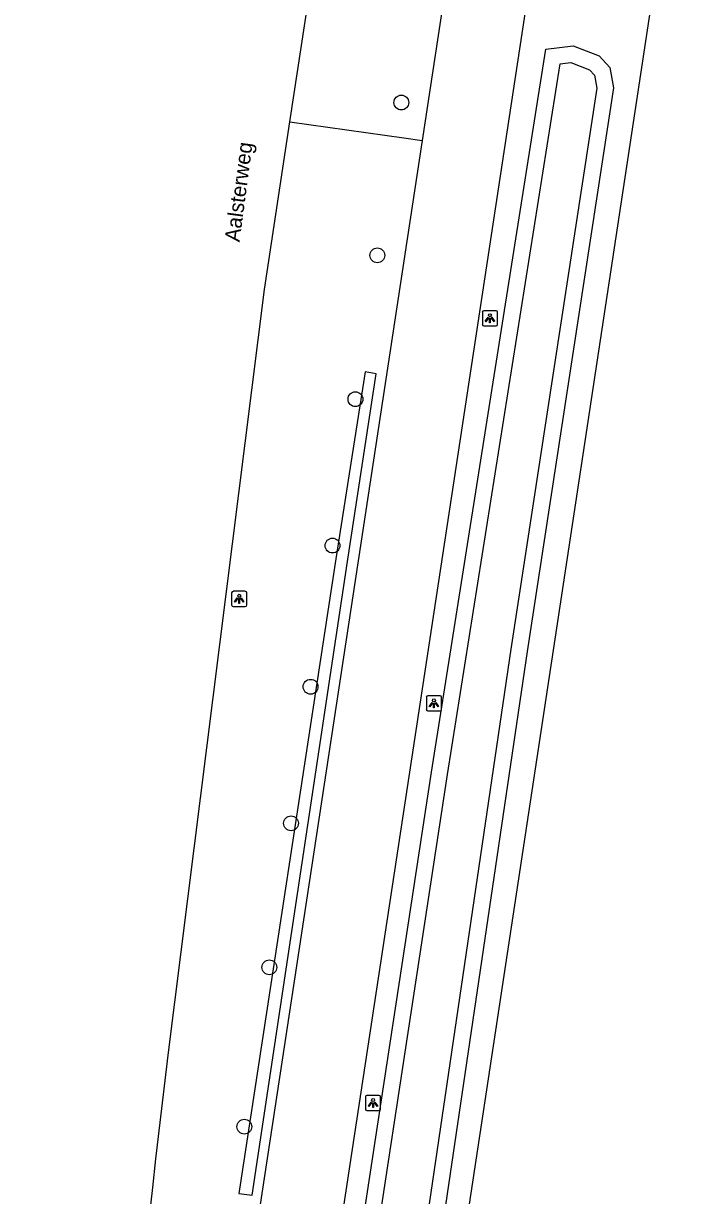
# Model space of a CAD drawing. Extents: x 161486 to 162249, y 379484 to 380829.
# Drawn here: x 161540.1 to 161583.9, y 379840.5 to 379917.8 of the extents above; entities that cross this region are included whole.
import ezdxf

# ---------------------------------------------------------------- set-up
doc = ezdxf.new("R2010")
doc.units = 0
for name, color, linetype in [('IMGEO_Berm_groen', 7, 'Continuous'), ('IMGEO_Boom', 7, 'Continuous'), ('IMGEO_Gemengd_bos', 7, 'Continuous'), ('IMGEO_Groenvoorziening', 7, 'Continuous'), ('IMGEO_Haag', 7, 'Continuous'), ('IMGEO_Lichtpunt', 7, 'Continuous'), ('IMGEO_Openbare_ruimte_label', 7, 'Continuous'), ('IMGEO_Rijbaan_lokaal_open', 7, 'Continuous'), ('IMGEO_Rijbaan_regionaal_gesloten', 7, 'Continuous'), ('IMGEO_Waterloop', 7, 'Continuous')]:
    doc.layers.add(name, color=color, linetype=linetype)

msp = doc.modelspace()

# ---------------------------------------------------------------- linework, layer by layer
at = {"layer": 'IMGEO_Berm_groen'}
msp.add_lwpolyline([(161557.693, 379911.327), (161565.21, 379910.272), (161566.417, 379910.103)], dxfattribs=at)
at = {"layer": 'IMGEO_Boom'}
for centre in [(161565.046, 379912.61), (161563.466, 379902.523), (161562.018, 379893.035), (161560.505, 379883.376), (161559.056, 379874.058), (161557.771, 379865.048), (161556.339, 379855.542), (161554.684, 379845.029)]:
    msp.add_circle(centre, 0.489, dxfattribs=at)
at = {"layer": 'IMGEO_Gemengd_bos'}
msp.add_lwpolyline([(161583.938, 379934.952), (161568.827, 379835.279), (161557.114, 379758.02)], dxfattribs=at)
at = {"layer": 'IMGEO_Groenvoorziening'}
msp.add_lwpolyline([(161579.042, 379913.572), (161573.346, 379876.388), (161565.066, 379820.159), (161564.384, 379818.933), (161559.643, 379819.959), (161567.034, 379868.426), (161574.594, 379916.137), (161576.379, 379916.357), (161578.094, 379915.687), (161578.809, 379914.928), (161579.042, 379913.572)], dxfattribs=at)
at = {"layer": 'IMGEO_Haag'}
msp.add_lwpolyline([(161561.497, 379882.333), (161563.397, 379894.707), (161562.657, 379894.836), (161560.722, 379882.51), (161554.328, 379840.615), (161555.212, 379840.511), (161561.497, 379882.333)], dxfattribs=at)
at = {"layer": 'IMGEO_Lichtpunt'}
for p, q in [((161571.296, 379898.87), (161570.488, 379898.87)), ((161571.296, 379898.87), (161570.488, 379898.87)), ((161570.394, 379898.775), (161570.394, 379897.968)), ((161570.394, 379898.775), (161570.394, 379897.968)), ((161571.39, 379897.968), (161571.39, 379898.775)), ((161571.39, 379897.968), (161571.39, 379898.775)), ((161570.488, 379897.874), (161571.296, 379897.874)), ((161570.488, 379897.874), (161571.296, 379897.874)), ((161554.752, 379880.356), (161553.944, 379880.356)), ((161554.752, 379880.356), (161553.944, 379880.356)), ((161553.85, 379880.261), (161553.85, 379879.454)), ((161553.85, 379880.261), (161553.85, 379879.454)), ((161554.846, 379879.454), (161554.846, 379880.261)), ((161554.846, 379879.454), (161554.846, 379880.261)), ((161553.944, 379879.36), (161554.752, 379879.36)), ((161553.944, 379879.36), (161554.752, 379879.36)), ((161566.698, 379873.365), (161566.698, 379872.558)), ((161566.698, 379873.365), (161566.698, 379872.558)), ((161567.6, 379873.46), (161566.792, 379873.46)), ((161567.6, 379873.46), (161566.792, 379873.46)), ((161567.694, 379872.558), (161567.694, 379873.365)), ((161567.694, 379872.558), (161567.694, 379873.365)), ((161566.792, 379872.464), (161567.6, 379872.464)), ((161566.792, 379872.464), (161567.6, 379872.464)), ((161563.587, 379847.089), (161562.779, 379847.089)), ((161563.587, 379847.089), (161562.779, 379847.089)), ((161562.685, 379846.994), (161562.685, 379846.187)), ((161562.685, 379846.994), (161562.685, 379846.187)), ((161563.681, 379846.187), (161563.681, 379846.994)), ((161563.681, 379846.187), (161563.681, 379846.994)), ((161562.779, 379846.093), (161563.587, 379846.093)), ((161562.779, 379846.093), (161563.587, 379846.093))]:
    msp.add_line(p, q, dxfattribs=at)
for points in [[(161570.768, 379898.439), (161570.807, 379898.411), (161570.619, 379898.149), (161570.581, 379898.176), (161570.768, 379898.439)], [(161570.87, 379898.391), (161570.917, 379898.391), (161570.917, 379898.069), (161570.87, 379898.069), (161570.87, 379898.391)], [(161570.98, 379898.411), (161571.018, 379898.438), (161571.205, 379898.176), (161571.166, 379898.148), (161570.98, 379898.411)], [(161554.224, 379879.925), (161554.263, 379879.897), (161554.075, 379879.635), (161554.037, 379879.662), (161554.224, 379879.925)], [(161554.326, 379879.877), (161554.373, 379879.877), (161554.373, 379879.555), (161554.326, 379879.555), (161554.326, 379879.877)], [(161554.436, 379879.897), (161554.474, 379879.924), (161554.661, 379879.662), (161554.622, 379879.634), (161554.436, 379879.897)], [(161567.072, 379873.029), (161567.111, 379873.001), (161566.923, 379872.739), (161566.885, 379872.766), (161567.072, 379873.029)], [(161567.174, 379872.981), (161567.221, 379872.981), (161567.221, 379872.659), (161567.174, 379872.659), (161567.174, 379872.981)], [(161567.284, 379873.001), (161567.322, 379873.028), (161567.509, 379872.766), (161567.47, 379872.738), (161567.284, 379873.001)], [(161563.059, 379846.658), (161563.098, 379846.63), (161562.91, 379846.368), (161562.872, 379846.395), (161563.059, 379846.658)], [(161563.161, 379846.61), (161563.208, 379846.61), (161563.208, 379846.288), (161563.161, 379846.288), (161563.161, 379846.61)], [(161563.271, 379846.63), (161563.309, 379846.657), (161563.496, 379846.395), (161563.457, 379846.367), (161563.271, 379846.63)]]:
    msp.add_lwpolyline(points, dxfattribs=at)
for centre in [(161570.893, 379898.573), (161554.349, 379880.059), (161567.197, 379873.163), (161563.184, 379846.792)]:
    msp.add_circle(centre, 0.0994, dxfattribs=at)
for centre, start, end in [((161570.488, 379898.775), 90, 180), ((161570.488, 379898.775), 90, 180), ((161571.296, 379898.775), 0, 90), ((161571.296, 379898.775), 0, 90), ((161570.488, 379897.968), 180, 270), ((161570.488, 379897.968), 180, 270), ((161571.296, 379897.968), 270, 0), ((161571.296, 379897.968), 270, 360), ((161553.944, 379880.261), 90, 180), ((161553.944, 379880.261), 90, 180), ((161554.752, 379880.261), 0, 90), ((161554.752, 379880.261), 0, 90), ((161553.944, 379879.454), 180, 270), ((161553.944, 379879.454), 180, 270), ((161554.752, 379879.454), 270, 0), ((161554.752, 379879.454), 270, 360), ((161566.792, 379873.365), 90, 180), ((161566.792, 379873.365), 90, 180), ((161567.6, 379873.365), 0, 90), ((161567.6, 379873.365), 0, 90), ((161566.792, 379872.558), 180, 270), ((161566.792, 379872.558), 180, 270), ((161567.6, 379872.558), 270, 0), ((161567.6, 379872.558), 270, 360), ((161562.779, 379846.994), 90, 180), ((161562.779, 379846.994), 90, 180), ((161563.587, 379846.994), 0, 90), ((161563.587, 379846.994), 0, 90), ((161562.779, 379846.187), 180, 270), ((161562.779, 379846.187), 180, 270), ((161563.587, 379846.187), 270, 0), ((161563.587, 379846.187), 270, 360)]:
    msp.add_arc(centre, 0.0946, start, end, dxfattribs=at)
at = {"layer": 'IMGEO_Rijbaan_lokaal_open'}
for points in [[(161574.263, 379936.392), (161574.118, 379934.45), (161574.401, 379931.306), (161574.489, 379927.649), (161574.039, 379923.973), (161560.773, 379836.759), (161558.436, 379821.396), (161558.059, 379819.043), (161557.417, 379814.852), (161556.702, 379809.458), (161556.07, 379805.38), (161554.769, 379796.716), (161550.698, 379765.372), (161550.328, 379761.55)], [(161568.671, 379924.979), (161568.639, 379924.714), (161566.417, 379910.103)], [(161566.417, 379910.103), (161555.385, 379837.579), (161553.583, 379825.732)]]:
    msp.add_lwpolyline(points, dxfattribs=at)
at = {"layer": 'IMGEO_Rijbaan_regionaal_gesloten'}
for points in [[(161557.693, 379911.327), (161561.114, 379933.819)], [(161540.108, 379760.615), (161541.483, 379775.689), (161542.991, 379790.84), (161543.902, 379799.222), (161544.154, 379801.546), (161544.174, 379801.742), (161544.225, 379802.254), (161545.482, 379814.716), (161546.135, 379819.933), (161546.428, 379824.038), (161546.834, 379827.017), (161547.079, 379827.822), (161548.103, 379836.152), (161548.651, 379841.02), (161548.842, 379842.908), (161549.676, 379849.933), (161556.011, 379900.267), (161557.693, 379911.327)], [(161546.834, 379827.017), (161547.079, 379827.822), (161548.103, 379836.152), (161548.651, 379841.02), (161548.842, 379842.908), (161549.676, 379849.933), (161556.011, 379900.267), (161557.693, 379911.327)]]:
    msp.add_lwpolyline(points, dxfattribs=at)
at = {"layer": 'IMGEO_Waterloop'}
msp.add_lwpolyline([(161568.103, 379868.26), (161575.535, 379915.163), (161576.24, 379915.25), (161577.474, 379914.768), (161577.798, 379914.424), (161577.946, 379913.562), (161572.276, 379876.549), (161564.025, 379820.512), (161563.829, 379820.16), (161560.866, 379820.801), (161568.103, 379868.26)], dxfattribs=at)

# ---------------------------------------------------------------- texts
at = {"layer": 'IMGEO_Openbare_ruimte_label'}
msp.add_text('Aalsterweg', height=1, rotation=82.46975, dxfattribs=at).set_placement((161554.369, 379903.375))

doc.saveas('drawing.dxf')
